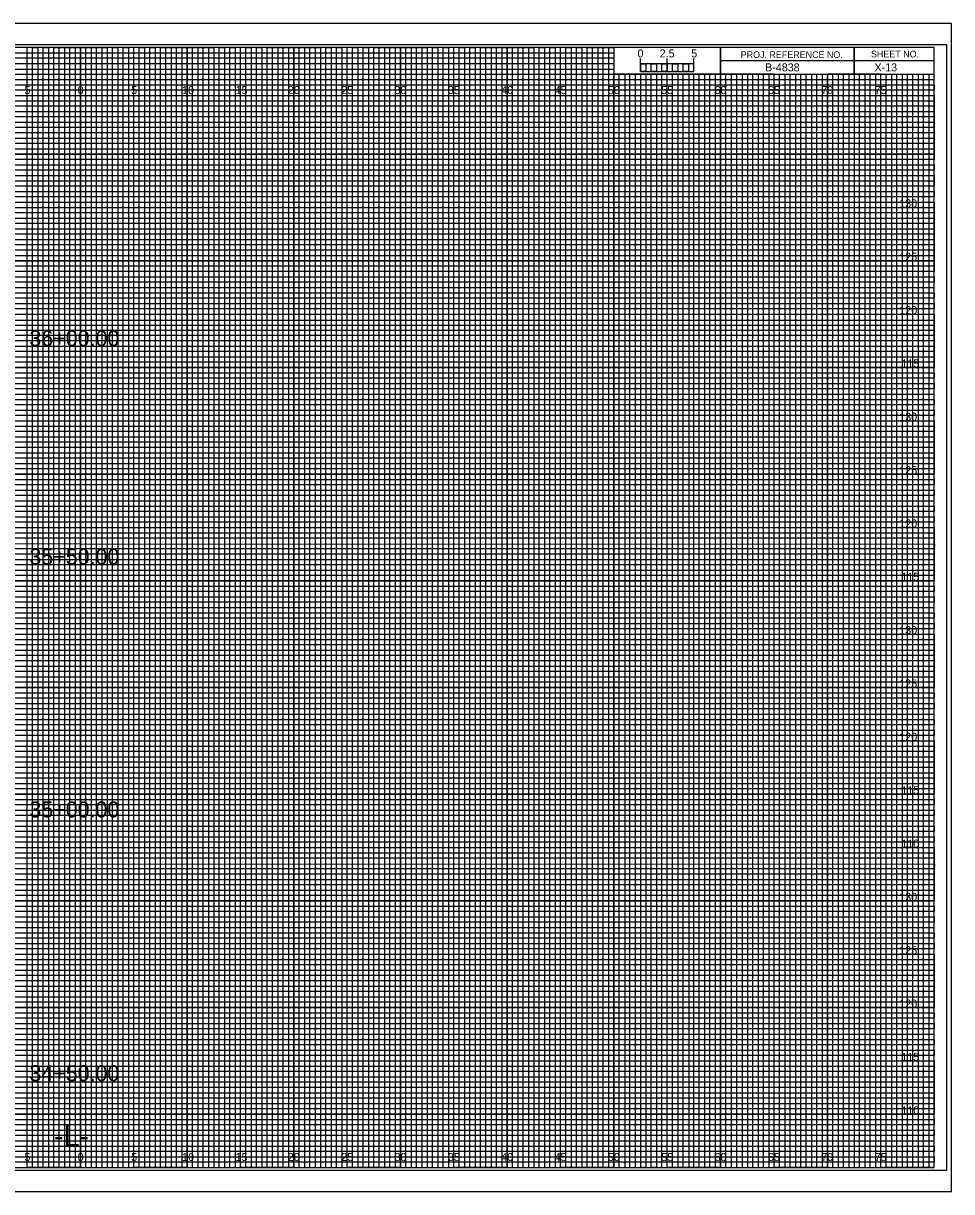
# Model space of a CAD drawing. Extents: x -7 to 182, y -2 to 1647.
# Drawn here: x 74.6 to 161.7, y 1207.8 to 1317.2 of the extents above; entities that cross this region are included whole.
import ezdxf

# ---------------------------------------------------------------- set-up
doc = ezdxf.new("R2010")
doc.units = 0
for name, color, linetype in [('Exist CMT Pavement', 7, 'Continuous'), ('Exist Cross Section Cell', 7, 'Continuous'), ('Exist XS Ground Line', 7, 'Continuous'), ('Prop CMT Pvmt Course 1', 7, 'Continuous'), ('Prop CMT Pvmt Course 2', 7, 'Continuous'), ('Prop CMT Pvmt Course 2 Wedge', 7, 'Continuous'), ('Prop CMT Pvmt Course 3', 7, 'Continuous'), ('Prop CMT Pvmt Surface', 7, 'Continuous'), ('Prop CMT Pvmt Surface Shoulder', 7, 'Continuous'), ('Prop CMT Pvmt Wedge Surface 1', 7, 'Continuous'), ('Prop CMT Pvmt Wedge Surface 2', 7, 'Continuous'), ('Prop CMT Pvmt Wedge Surface 3', 7, 'Continuous'), ('Prop CMT Shld Paved Course 1', 7, 'Continuous'), ('Prop CMT Shld Paved Course 2', 7, 'Continuous'), ('Prop CMT Shld Paved Course 3', 7, 'Continuous'), ('Prop CMT Slope Grass', 7, 'Continuous'), ('Prop CMT Subgrade Earthwork', 7, 'Continuous')]:
    doc.layers.add(name, color=color, linetype=linetype)

msp = doc.modelspace()

# ---------------------------------------------------------------- linework, layer by layer
at = {"layer": 'Exist XS Ground Line'}
for p, q in [((75, 1315), (70, 1315)), ((75, 1210), (75, 1315)), ((85, 1315), (80, 1315)), ((80, 1315), (80, 1210)), ((85, 1210), (85, 1315)), ((95, 1315), (90, 1315)), ((90, 1315), (90, 1210)), ((95, 1210), (95, 1315)), ((105, 1315), (100, 1315)), ((100, 1315), (100, 1210)), ((105, 1210), (105, 1315)), ((115, 1315), (110, 1315)), ((110, 1315), (110, 1210)), ((115, 1210), (115, 1315)), ((125, 1315), (120, 1315)), ((120, 1315), (120, 1210)), ((125, 1210), (125, 1315)), ((130, 1315), (130, 1210)), ((135, 1210), (135, 1312.5)), ((145, 1312.5), (140, 1312.5)), ((140, 1312.5), (140, 1210)), ((145, 1210), (145, 1312.5)), ((155, 1312.5), (150, 1312.5)), ((150, 1312.5), (150, 1210)), ((155, 1210), (155, 1312.5)), ((80, 1210), (75, 1210)), ((90, 1210), (85, 1210)), ((100, 1210), (95, 1210)), ((110, 1210), (105, 1210)), ((120, 1210), (115, 1210)), ((130, 1210), (125, 1210)), ((140, 1210), (135, 1210)), ((150, 1210), (145, 1210)), ((160, 1210), (155, 1210)), ((160, 1210), (160, 1210))]:
    msp.add_line(p, q, dxfattribs=at)
for points in [[(0, 1310), (160, 1310), (160, 1305), (0, 1305)], [(0, 1300), (160, 1300), (160, 1295), (0, 1295)], [(0, 1290), (160, 1290), (160, 1285), (0, 1285)], [(0, 1280), (160, 1280), (160, 1275), (0, 1275)], [(0, 1270), (160, 1270), (160, 1265), (0, 1265)], [(0, 1260), (160, 1260), (160, 1255), (0, 1255)], [(0, 1250), (160, 1250), (160, 1245), (0, 1245)], [(0, 1240), (160, 1240), (160, 1235), (0, 1235)], [(0, 1230), (160, 1230), (160, 1225), (0, 1225)], [(0, 1220), (160, 1220), (160, 1215), (0, 1215)]]:
    msp.add_lwpolyline(points, dxfattribs=at)
at = {"layer": 'Prop CMT Pvmt Course 2'}
for p, q in [((132.5, 1312.75), (132.5, 1313.95)), ((132.5, 1313.45), (132.5, 1313.95)), ((135, 1312.75), (135, 1313.95)), ((137.5, 1312.75), (137.5, 1313.95)), ((137.5, 1313.45), (137.5, 1313.95))]:
    msp.add_line(p, q, dxfattribs=at)
for points in [[(137.5, 1313.45), (132.5, 1313.45), (132.5, 1312.75), (137.5, 1312.75)], [(132.5, 1313.45), (133, 1313.45), (133, 1312.75), (132.5, 1312.75)], [(133.5, 1313.45), (134, 1313.45), (134, 1312.75), (133.5, 1312.75)], [(134.5, 1313.45), (135, 1313.45), (135, 1312.75), (134.5, 1312.75)], [(135.5, 1313.45), (136, 1313.45), (136, 1312.75), (135.5, 1312.75)], [(136.5, 1313.45), (137, 1313.45), (137, 1312.75), (136.5, 1312.75)]]:
    msp.add_lwpolyline(points, close=True, dxfattribs=at)
at = {"layer": 'Prop CMT Pvmt Course 3'}
msp.add_lwpolyline([(-6.7, 1207.75), (161.65, 1207.75), (161.65, 1317.25), (-6.7, 1317.25)], close=True, dxfattribs=at)
at = {"layer": 'Prop CMT Pvmt Wedge Surface 1'}
for p, q in [((0, 1314.5), (130, 1314.5)), ((130, 1314.5), (130, 1313.99)), ((130, 1313.99), (0, 1313.99)), ((0, 1313.5), (130, 1313.5)), ((130, 1312.94), (0, 1312.94)), ((130, 1313.5), (130, 1312.94)), ((0, 1312), (160, 1312))]:
    msp.add_line(p, q, dxfattribs=at)
for points in [[(0, 1311.5), (135, 1311.5), (160, 1311.5), (160, 1311), (0, 1311)], [(0, 1310.5), (160, 1310.5), (160, 1309.5), (0, 1309.5)], [(0, 1309), (160, 1309), (160, 1308.5), (0, 1308.49)], [(0, 1308), (160, 1308), (160, 1307), (0, 1307)], [(0, 1306.5), (160, 1306.5), (160, 1306), (0, 1306)], [(0, 1305.5), (160, 1305.5), (160, 1304.5), (0, 1304.5)], [(0, 1304), (160, 1304), (160, 1303.5), (0, 1303.5)], [(0, 1303), (160, 1303), (160, 1302), (0, 1302)], [(0, 1301.5), (160, 1301.5), (160, 1301), (0, 1301)], [(0, 1300.5), (160, 1300.5), (160, 1299.5), (0, 1299.5)], [(0, 1299), (160, 1299), (160, 1298.5), (0, 1298.5)], [(0, 1298), (160, 1298), (160, 1296.98), (160, 1296.5), (160, 1296), (0, 1296)], [(0, 1297), (160, 1297), (160, 1296.5), (0, 1296.5)], [(0, 1295.5), (160, 1295.5), (160, 1294.5), (0, 1294.52)], [(0, 1294.52), (160, 1294.5), (160, 1294), (0, 1294)], [(0, 1293.5), (160, 1293.5), (160, 1293), (0, 1293)], [(0, 1292), (160, 1292), (160, 1291.5), (0, 1291.5)], [(0, 1291), (160, 1291), (160, 1290.5), (0, 1290.5)], [(-0.04, 1289.44), (160, 1289.44), (160, 1288.94), (-0.04, 1288.94)], [(0, 1288.5), (160, 1288.5), (160, 1288), (0, 1288)], [(0, 1287), (160, 1287), (160, 1286.5), (0, 1286.5)], [(0, 1286), (160, 1286), (160, 1285.5), (0, 1285.5)], [(0, 1284.5), (160, 1284.5), (160, 1284), (0, 1284)], [(0, 1283.5), (160, 1283.5), (160, 1283), (0, 1283)], [(0, 1282), (160, 1282), (160, 1281.5), (0, 1281.5)], [(0, 1281), (160, 1281), (160, 1280.5), (0, 1280.5)], [(0, 1279.5), (160, 1279.5), (160, 1278.99), (0, 1279)], [(0, 1278.5), (160, 1278.5), (160, 1278), (0, 1278)], [(0, 1277), (160, 1277), (160, 1276.5), (0, 1276.5)], [(0, 1276), (160, 1276), (160, 1275.5), (0, 1275.5)], [(0, 1274.5), (160, 1274.5), (160, 1274), (0, 1274)], [(0, 1273.5), (160, 1273.5), (160, 1273), (0, 1273)], [(0, 1272), (160, 1272), (160, 1271.5), (0, 1271.5)], [(0, 1271), (160, 1271), (160, 1270.5), (0, 1270.5)], [(0, 1269.5), (160, 1269.5), (160, 1269), (0, 1269)], [(0, 1268.5), (160.03, 1268.45), (160, 1268), (0, 1268)], [(0, 1267), (160, 1267), (160, 1266.5), (0, 1266.5)], [(0, 1266), (160, 1266), (160, 1265.5), (0, 1265.5)], [(0, 1264.5), (160, 1264.5), (160, 1264), (0, 1264)], [(0, 1263.5), (160, 1263.5), (160, 1263), (0, 1263)], [(0, 1262), (160, 1262), (160, 1261.5), (0, 1261.5)], [(0, 1261), (160, 1261), (160, 1260.5), (0, 1260.5)], [(0, 1259.5), (160, 1259.5), (160, 1259), (0, 1259)], [(0, 1258.5), (160, 1258.5), (160, 1258), (0, 1258)], [(0, 1257), (160, 1257), (160, 1256.5), (0, 1256.5)], [(0, 1256), (160, 1256), (160, 1255.5), (0, 1255.5)], [(0, 1254.5), (160, 1254.5), (160, 1254), (0, 1254)], [(0, 1253.5), (160, 1253.5), (160, 1253), (0, 1253)], [(0, 1252), (160, 1252), (160, 1251.5), (0, 1251.5)], [(0, 1251), (160, 1251), (160, 1250.5), (0, 1250.5)], [(0, 1249.5), (160, 1249.5), (160, 1248.99), (0, 1249)], [(0, 1248.5), (160, 1248.5), (160, 1248), (0, 1248)], [(0, 1247), (160, 1247), (160, 1246.5), (0, 1246.5)], [(0, 1246), (160, 1246), (160, 1245.5), (0, 1245.5)], [(0, 1244.5), (160, 1244.5), (160, 1244), (0, 1244)], [(0, 1243.5), (160, 1243.5), (160, 1243), (0, 1243)], [(0, 1242), (160, 1242), (160, 1241.5), (0, 1241.5)], [(0, 1241), (160, 1241), (160, 1240.5), (0, 1240.5)], [(0, 1239.5), (160, 1239.5), (160, 1239), (0, 1239)], [(0, 1238.5), (160.03, 1238.45), (160, 1238), (0, 1238)], [(0, 1237), (160, 1237), (160, 1236.5), (0, 1236.5)], [(0, 1236), (160, 1236), (160, 1235.5), (0, 1235.5)], [(0, 1234.5), (160, 1234.5), (160, 1234), (0, 1234)], [(0, 1233.5), (160, 1233.5), (160, 1233), (0, 1233)], [(0, 1232), (160, 1232), (160, 1231.5), (0, 1231.5)], [(0, 1231), (160, 1231), (160, 1230.5), (0, 1230.5)], [(0, 1229.5), (160, 1229.5), (160, 1229), (0, 1229)], [(0, 1228.5), (160, 1228.5), (160, 1228), (0, 1228)], [(0, 1227), (160, 1227), (160, 1226.5), (0, 1226.5)], [(0, 1226), (160, 1226), (160, 1225.5), (0, 1225.5)], [(0, 1224.5), (160, 1224.5), (160, 1224), (0, 1224)], [(0, 1223.5), (160, 1223.5), (160, 1223), (0, 1223)], [(0, 1222), (160, 1222), (160, 1221.5), (0, 1221.5)], [(0, 1221), (160, 1221), (160, 1220.5), (0, 1220.5)], [(0, 1219.5), (160, 1219.5), (160, 1219), (0, 1219)], [(0, 1218.5), (160, 1218.5), (160, 1218), (0, 1218)], [(0, 1217), (160, 1217), (160, 1216.5), (0, 1216.5)], [(0, 1216), (160, 1216), (160, 1215.5), (0, 1215.5)], [(0, 1214.5), (160, 1214.5), (160, 1214), (0, 1214)], [(0, 1213.5), (160, 1213.5), (160, 1213), (0, 1213)], [(0, 1212), (160, 1212), (160, 1211.5), (0, 1211.5)], [(0, 1211), (160, 1211), (160, 1210.5), (0, 1210.5)]]:
    msp.add_lwpolyline(points, dxfattribs=at)
at = {"layer": 'Prop CMT Pvmt Wedge Surface 2'}
for p, q in [((152.5, 1315), (152.5, 1312.5)), ((152.5, 1312.5), (152.5, 1315)), ((160, 1313.75), (140, 1313.75)), ((140, 1313.75), (140, 1312.5)), ((140, 1312.5), (160, 1312.5))]:
    msp.add_line(p, q, dxfattribs=at)
for points in [[(160, 1315), (0, 1315), (0, 1210), (160, 1210)], [(140, 1315), (130, 1315), (130, 1312.52), (140, 1312.52)], [(160, 1315), (140, 1315), (140, 1312.5), (160, 1312.5)]]:
    msp.add_lwpolyline(points, close=True, dxfattribs=at)
at = {"layer": 'Prop CMT Pvmt Wedge Surface 3'}
for p, q in [((133.5, 1312.5), (133, 1312.5)), ((133, 1312.5), (133, 1210)), ((133.5, 1210), (133.5, 1312.5)), ((134.5, 1312.5), (134, 1312.5)), ((134, 1312.5), (134, 1210)), ((134.5, 1210), (134.5, 1312.5)), ((133, 1210), (132.5, 1210)), ((134, 1210), (133.5, 1210))]:
    msp.add_line(p, q, dxfattribs=at)
for points in [[(75, 1210), (75.5, 1210), (75.5, 1315), (76, 1315), (76, 1210)], [(76, 1210), (76.5, 1210), (76.5, 1315), (77, 1315), (77, 1210)], [(77.5, 1210), (78, 1210), (78, 1315), (78.5, 1315), (78.5, 1210)], [(78.5, 1210), (79, 1210), (79, 1315), (79.5, 1315), (79.5, 1210)], [(80, 1210), (80.5, 1210), (80.5, 1315), (81, 1315), (81, 1210)], [(81, 1210), (81.5, 1210), (81.5, 1315), (82, 1315), (82, 1210)], [(82.5, 1210), (83, 1210), (83, 1315), (83.5, 1315), (83.5, 1210)], [(83.5, 1210), (84, 1210), (84, 1315), (84.5, 1315), (84.5, 1210)], [(85, 1210), (85.5, 1210), (85.5, 1315), (86, 1315), (86, 1210)], [(86, 1210), (86.5, 1210), (86.5, 1315), (87, 1315), (87, 1210)], [(87.5, 1210), (88, 1210), (88, 1315), (88.5, 1315), (88.5, 1210)], [(88.5, 1210), (89, 1210), (89, 1315), (89.5, 1315), (89.5, 1210)], [(90, 1210), (90.5, 1210), (90.5, 1315), (91, 1315), (91, 1210)], [(91, 1210), (91.5, 1210), (91.5, 1315), (92, 1315), (92, 1210)], [(92.5, 1210), (93, 1210), (93, 1315), (93.5, 1315), (93.5, 1210)], [(93.5, 1210), (94, 1210), (94, 1315), (94.5, 1315), (94.5, 1210)], [(95, 1210), (95.5, 1210), (95.5, 1315), (96, 1315), (96, 1210)], [(96, 1210), (96.5, 1210), (96.5, 1315), (97, 1315), (97, 1210)], [(97.5, 1210), (98, 1210), (98, 1315), (98.5, 1315), (98.5, 1210)], [(98.5, 1210), (99, 1210), (99, 1315), (99.5, 1315), (99.5, 1210)], [(100, 1210), (100.5, 1210), (100.5, 1315), (101, 1315), (101, 1210)], [(101, 1210), (101.5, 1210), (101.5, 1315), (102, 1315), (102, 1210)], [(102.5, 1210), (103, 1210), (103, 1315), (103.5, 1315), (103.5, 1210)], [(103.5, 1210), (104, 1210), (104, 1315), (104.5, 1315), (104.5, 1210)], [(105, 1210), (105.5, 1210), (105.5, 1315), (106, 1315), (106, 1210)], [(106, 1210), (106.5, 1210), (106.5, 1315), (107, 1315), (107, 1210)], [(107.5, 1210), (108, 1210), (108, 1315), (108.5, 1315), (108.5, 1210)], [(108.5, 1210), (109, 1210), (109, 1315), (109.5, 1315), (109.5, 1210)], [(110, 1210), (110.5, 1210), (110.5, 1315), (111, 1315), (111, 1210)], [(111, 1210), (111.5, 1210), (111.5, 1315), (112, 1315), (112, 1210)], [(112.5, 1210), (113, 1210), (113, 1315), (113.5, 1315), (113.5, 1210)], [(113.5, 1210), (114, 1210), (114, 1315), (114.5, 1315), (114.5, 1210)], [(115, 1210), (115.5, 1210), (115.5, 1315), (116, 1315), (116, 1210)], [(116, 1210), (116.5, 1210), (116.5, 1315), (117, 1315), (117, 1210)], [(117.5, 1210), (118, 1210), (118, 1315), (118.5, 1315), (118.5, 1210)], [(118.5, 1210), (119, 1210), (119, 1315), (119.5, 1315), (119.5, 1210)], [(120, 1210), (120.5, 1210), (120.5, 1315), (121, 1315), (121, 1210)], [(121, 1210), (121.5, 1210), (121.5, 1315), (122, 1315), (122, 1210)], [(122.5, 1210), (123, 1210), (123, 1315), (123.5, 1315), (123.5, 1210)], [(123.5, 1210), (124, 1210), (124, 1315), (124.5, 1315), (124.5, 1210)], [(125, 1210), (125.5, 1210), (125.5, 1315), (126, 1315), (126, 1210)], [(126, 1210), (126.5, 1210), (126.5, 1315), (127, 1315), (127, 1210)], [(127.5, 1210), (128, 1210), (128, 1315), (128.5, 1315), (128.5, 1210)], [(128.5, 1210), (129, 1210), (129, 1315), (129.5, 1315), (129.5, 1210)], [(130, 1210), (130.5, 1210), (130.5, 1312.5), (131.01, 1312.5), (131.01, 1210)], [(131, 1210), (131.5, 1210), (131.5, 1312.5), (132, 1312.5), (132, 1210)], [(135, 1210), (135.49, 1210), (135.49, 1312.5), (136, 1312.5), (136, 1210)], [(136, 1210), (136.5, 1210), (136.5, 1312.5), (137.03, 1312.5), (137.03, 1210)], [(137.5, 1210), (138, 1210), (138, 1312.5), (138.5, 1312.5), (138.5, 1210)], [(138.5, 1210), (139, 1210), (139, 1312.5), (139.5, 1312.5), (139.5, 1210)], [(140, 1210), (140.5, 1210), (140.5, 1312.5), (141, 1312.5), (141, 1210)], [(141, 1210), (141.5, 1210), (141.5, 1312.5), (142, 1312.5), (142, 1210)], [(142.5, 1210), (143, 1210), (143, 1312.5), (143.5, 1312.5), (143.5, 1210)], [(143.5, 1210), (144, 1210), (144, 1312.5), (144.5, 1312.5), (144.5, 1210)], [(145, 1210), (145.5, 1210), (145.5, 1312.5), (146, 1312.5), (146, 1210)], [(146, 1210), (146.5, 1210), (146.5, 1312.5), (147, 1312.5), (147, 1210)], [(147.5, 1210), (148, 1210), (148, 1312.5), (148.5, 1312.5), (148.5, 1210)], [(148.5, 1210), (149, 1210), (149, 1312.5), (149.5, 1312.5), (149.5, 1210)], [(150, 1210), (150.5, 1210), (150.5, 1312.5), (151, 1312.5), (151, 1210)], [(151, 1210), (151.5, 1210), (151.5, 1312.5), (152, 1312.5), (152, 1210)], [(152.5, 1210), (153, 1210), (153, 1312.5), (153.5, 1312.5), (153.5, 1210)], [(153.5, 1210), (154, 1210), (154, 1312.5), (154.5, 1312.5), (154.5, 1210)], [(155, 1210), (155.5, 1210), (155.5, 1312.5), (156, 1312.5), (156, 1210)], [(156, 1210), (156.5, 1210), (156.5, 1312.5), (157, 1312.5), (157, 1210)], [(157.5, 1210), (158, 1210), (158, 1312.5), (158.5, 1312.5), (158.5, 1210)], [(158.5, 1210), (159, 1210), (159, 1312.5), (159.5, 1312.5), (159.5, 1210)]]:
    msp.add_lwpolyline(points, dxfattribs=at)
at = {"layer": 'Prop CMT Shld Paved Course 1'}
for p, q in [((75, 1210), (75, 1315)), ((80, 1210), (80, 1315)), ((85, 1210), (85, 1315)), ((90, 1210), (90, 1315)), ((95, 1210), (95, 1315)), ((100, 1210), (100, 1315)), ((105, 1210), (105, 1315)), ((110, 1210), (110, 1315)), ((115, 1210), (115, 1315)), ((120, 1210), (120, 1315)), ((125, 1210), (125, 1315)), ((130, 1210), (130, 1312.34)), ((135, 1210), (135, 1312.34)), ((140, 1210), (140, 1312.34)), ((145, 1210), (145, 1312.34)), ((150, 1210), (150, 1312.34)), ((155, 1210), (155, 1312.34)), ((0, 1310), (160, 1310)), ((0, 1305), (160, 1305)), ((0, 1300), (160, 1300)), ((0, 1295), (160, 1295)), ((0, 1290), (160, 1290)), ((0, 1285), (160, 1285)), ((0, 1280), (160, 1280)), ((0, 1275), (160, 1275)), ((0, 1270), (160, 1270)), ((0, 1265), (160, 1265)), ((0, 1260), (160, 1260)), ((0, 1255), (160, 1255)), ((0, 1250), (160, 1250)), ((0, 1245), (160, 1245)), ((0, 1240), (160, 1240)), ((0, 1235), (160, 1235)), ((0, 1230), (160, 1230)), ((0, 1225), (160, 1225)), ((0, 1220), (160, 1220)), ((0, 1215), (160, 1215))]:
    msp.add_line(p, q, dxfattribs=at)
at = {"layer": 'Prop CMT Shld Paved Course 2'}
for p, q in [((161.65, 1317.25), (-6.7, 1317.25)), ((-6.7, 1207.75), (161.65, 1207.75))]:
    msp.add_line(p, q, dxfattribs=at)
at = {"layer": 'Prop CMT Slope Grass'}
msp.add_lwpolyline([(-5.4, 1209.75), (161.2, 1209.75), (161.2, 1315.25), (-5.4, 1315.25)], close=True, dxfattribs=at)
at = {"layer": 'Prop CMT Subgrade Earthwork'}
for points in [[(72.5, 1210), (77.5, 1210), (77.5, 1315), (82.5, 1315), (82.5, 1210), (87.5, 1210), (87.5, 1315), (92.5, 1315), (92.5, 1210), (97.5, 1210), (97.5, 1315), (102.5, 1315), (102.5, 1210), (107.5, 1210), (107.5, 1315), (112.5, 1315), (112.5, 1210), (117.5, 1210), (117.5, 1315), (122.5, 1315), (122.5, 1210), (127.5, 1210), (127.5, 1315), (129.97, 1315), (130, 1315), (130, 1312.5), (132.5, 1312.5), (132.5, 1210), (137.5, 1210), (137.5, 1312.5), (142.5, 1312.5), (142.5, 1210), (147.5, 1210), (147.5, 1312.5), (152.5, 1312.5), (152.5, 1210), (157.5, 1210), (157.5, 1312.5)], [(0, 1312.5), (137.5, 1312.5)], [(0, 1302.5), (160, 1302.5), (160, 1307.5), (0, 1307.5)], [(0, 1292.5), (160, 1292.5), (160, 1297.5), (0, 1297.5)], [(0, 1282.5), (160, 1282.5), (160, 1287.5), (0, 1287.5)], [(0, 1272.5), (160, 1272.5), (160, 1277.5), (0, 1277.5)], [(0, 1262.5), (160, 1262.5), (160, 1267.5), (0, 1267.5)], [(0, 1252.5), (160, 1252.5), (160, 1257.5), (0, 1257.5)], [(0, 1242.5), (160, 1242.5), (160, 1247.5), (0, 1247.5)], [(0, 1232.5), (160, 1232.5), (160, 1237.5), (0, 1237.5)], [(0, 1222.5), (160, 1222.5), (160, 1227.5), (0, 1227.5)], [(0, 1212.5), (160, 1212.5), (160, 1217.5), (0, 1217.5)]]:
    msp.add_lwpolyline(points, dxfattribs=at)

# ---------------------------------------------------------------- texts
at = {"layer": 'Exist CMT Pavement'}
for s, p in [('36+00.00', (75.21, 1286.99)), ('35+50.00', (75.21, 1266.52)), ('35+00.00', (75.21, 1242.82)), ('34+50.00', (75.21, 1218.1))]:
    msp.add_text(s, height=1.5, dxfattribs=at).set_placement(p)
at = {"layer": 'Exist Cross Section Cell'}
for s, p in [('5', (74.74, 1310.62)), ('0', (79.73, 1310.62)), ('0', (79.73, 1310.62)), ('5', (84.74, 1310.62)), ('10', (89.52, 1310.62)), ('15', (94.53, 1310.62)), ('20', (99.43, 1310.62)), ('25', (104.44, 1310.62)), ('30', (109.43, 1310.62)), ('35', (114.44, 1310.62)), ('40', (119.43, 1310.62)), ('45', (124.44, 1310.62)), ('50', (129.43, 1310.62)), ('55', (134.44, 1310.62)), ('60', (139.43, 1310.62)), ('65', (144.44, 1310.62)), ('70', (149.43, 1310.62)), ('75', (154.44, 1310.62)), ('5', (74.74, 1210.62)), ('0', (79.73, 1210.62)), ('0', (79.73, 1210.62)), ('5', (84.74, 1210.62)), ('10', (89.52, 1210.62)), ('15', (94.53, 1210.62)), ('20', (99.43, 1210.62)), ('25', (104.44, 1210.62)), ('30', (109.43, 1210.62)), ('35', (114.44, 1210.62)), ('40', (119.43, 1210.62)), ('45', (124.44, 1210.62)), ('50', (129.43, 1210.62)), ('55', (134.44, 1210.62)), ('60', (139.43, 1210.62)), ('65', (144.44, 1210.62)), ('70', (149.43, 1210.62)), ('75', (154.44, 1210.62))]:
    msp.add_text(s, height=0.75, dxfattribs=at).set_placement(p)
at = {"layer": 'Prop CMT Pvmt Course 1'}
msp.add_text('-L-', height=2, dxfattribs=at).set_placement((77.53, 1212))
at = {"layer": 'Prop CMT Pvmt Course 2'}
msp.add_text('0', height=0.75, dxfattribs=at).set_placement((132.21, 1314.06))
at = {"layer": 'Prop CMT Pvmt Course 2 Wedge'}
for s, p in [('2.5', (134.29, 1314.06)), ('5', (137.24, 1314.06))]:
    msp.add_text(s, height=0.75, dxfattribs=at).set_placement(p)
at = {"layer": 'Prop CMT Pvmt Surface'}
msp.add_text('X-13', height=0.75, dxfattribs=at).set_placement((154.42, 1312.75))
at = {"layer": 'Prop CMT Pvmt Surface Shoulder'}
msp.add_text('B-4838', height=0.75, dxfattribs=at).set_placement((144.17, 1312.75))
at = {"layer": 'Prop CMT Pvmt Wedge Surface 2'}
for s, p in [('PROJ. REFERENCE NO.', (141.88, 1314)), ('SHEET NO.', (154.09, 1314.06))]:
    msp.add_text(s, height=0.625, dxfattribs=at).set_placement(p)
at = {"layer": 'Prop CMT Shld Paved Course 3'}
for s, p in [('130', (156.74, 1300)), ('125', (156.74, 1295)), ('120', (156.75, 1290)), ('115', (156.93, 1285)), ('130', (156.74, 1280)), ('125', (156.74, 1275)), ('120', (156.75, 1270)), ('115', (156.93, 1265)), ('130', (156.74, 1260)), ('125', (156.74, 1255)), ('120', (156.75, 1250)), ('115', (156.93, 1245)), ('110', (156.94, 1240)), ('130', (156.74, 1235)), ('125', (156.74, 1230)), ('120', (156.75, 1225)), ('115', (156.93, 1220)), ('110', (156.94, 1215))]:
    msp.add_text(s, height=0.75, dxfattribs=at).set_placement(p)

doc.saveas('drawing.dxf')
